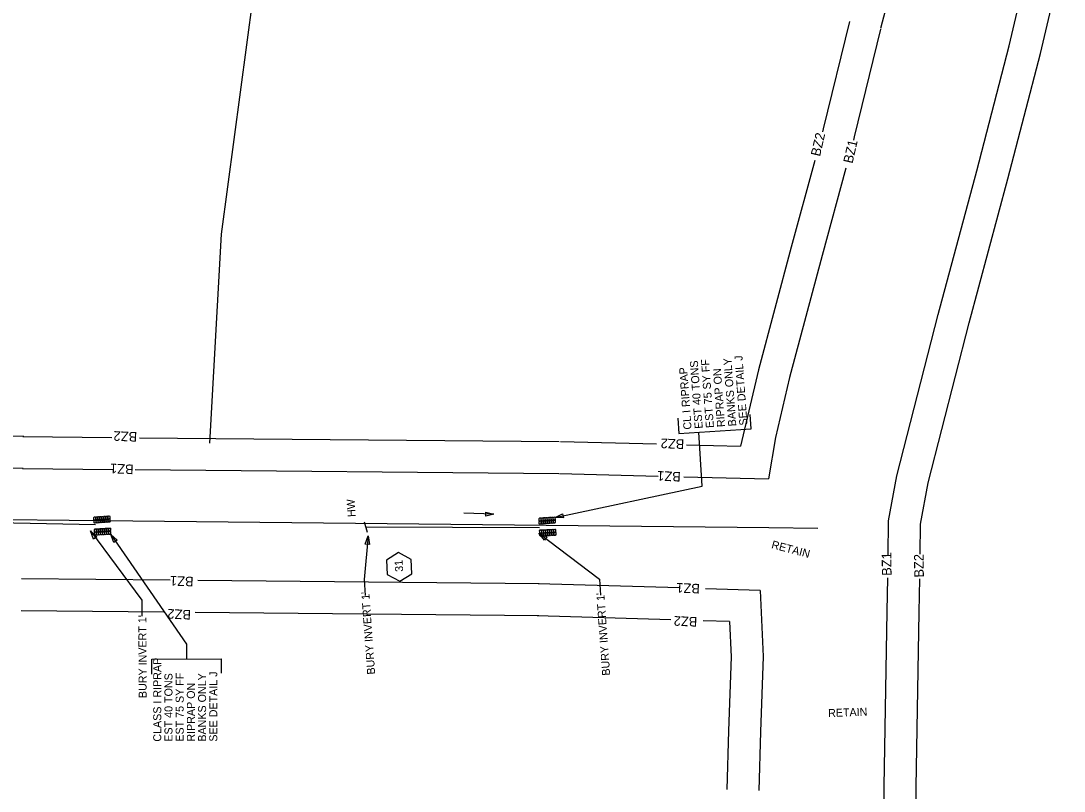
# Model space of a CAD drawing. Extents: x 2384780 to 2405432, y 547869 to 573706.
# Drawn here: x 2395243 to 2395895, y 555848 to 556329 of the extents above; entities that cross this region are included whole.
import ezdxf

# ---------------------------------------------------------------- set-up
doc = ezdxf.new("R2010")
doc.units = 0
for name, color, linetype in [('Old_Level_1', 7, 'Continuous'), ('Old_Level_19', 7, 'Continuous'), ('Old_Level_23', 7, 'Continuous'), ('Old_Level_5', 7, 'Continuous'), ('Old_Level_6', 7, 'Continuous'), ('Prop Buffer Zone 1', 7, 'Continuous'), ('Prop Buffer Zone 2', 7, 'Continuous'), ('Prop Drainage Box Number Symbol CELL', 7, 'Continuous'), ('Prop Drop Inlet Text', 7, 'Continuous')]:
    doc.layers.add(name, color=color, linetype=linetype)

# ---------------------------------------------------------------- blocks, each defined once
blk = doc.blocks.new('AH1')
at = {"layer": 'Old_Level_23'}
blk.add_lwpolyline([(-5.28, 1.32), (0, 0), (-5.28, -1.32)], close=True, dxfattribs=at)
blk = doc.blocks.new('RRA')
at = {"layer": 'Old_Level_1'}
for p, q in [((0, 0.078), (0.2, 0.078)), ((0, 0.04), (0.2, 0.04)), ((0.2, -0.04), (0, -0.04)), ((0.2, -0.078), (0, -0.078))]:
    blk.add_line(p, q, dxfattribs=at)
for points in [[(0.0235, 0.115), (0.025, 0.103), (0.025, 0.0815), (0.01, 0.0745), (0, 0.078), (0.0015, 0.1065), (0.01175, 0.115), (0.0235, 0.115)], [(0.0235, 0.077), (0.025, 0.065), (0.025, 0.0435), (0.01, 0.0365), (0, 0.04), (0.0015, 0.0685), (0.01175, 0.077), (0.0235, 0.077)], [(0.0485, 0.115), (0.05025, 0.103), (0.05025, 0.0815), (0.035, 0.0745), (0.025, 0.078), (0.02675, 0.1065), (0.037, 0.115), (0.0485, 0.115)], [(0.0485, 0.077), (0.05025, 0.065), (0.05025, 0.0435), (0.035, 0.0365), (0.025, 0.04), (0.02675, 0.0685), (0.037, 0.077), (0.0485, 0.077)], [(0.07375, 0.115), (0.0755, 0.103), (0.0755, 0.0815), (0.06025, 0.0745), (0.05025, 0.078), (0.052, 0.1065), (0.062, 0.115), (0.07375, 0.115)], [(0.07375, 0.077), (0.0755, 0.065), (0.0755, 0.0435), (0.06025, 0.0365), (0.05025, 0.04), (0.052, 0.0685), (0.062, 0.077), (0.07375, 0.077)], [(0.099, 0.115), (0.1005, 0.103), (0.1005, 0.0815), (0.0855, 0.0745), (0.0755, 0.078), (0.077, 0.1065), (0.087, 0.115), (0.099, 0.115)], [(0.099, 0.077), (0.1005, 0.065), (0.1005, 0.0435), (0.0855, 0.0365), (0.0755, 0.04), (0.077, 0.0685), (0.087, 0.077), (0.099, 0.077)], [(0.124, 0.115), (0.1255, 0.103), (0.1255, 0.0815), (0.1105, 0.0745), (0.1005, 0.078), (0.102, 0.1065), (0.11225, 0.115), (0.124, 0.115)], [(0.124, 0.077), (0.1255, 0.065), (0.1255, 0.0435), (0.1105, 0.0365), (0.1005, 0.04), (0.102, 0.0685), (0.11225, 0.077), (0.124, 0.077)], [(0.149, 0.115), (0.15075, 0.103), (0.15075, 0.0815), (0.1355, 0.0745), (0.1255, 0.078), (0.12725, 0.1065), (0.1375, 0.115), (0.149, 0.115)], [(0.149, 0.077), (0.15075, 0.065), (0.15075, 0.0435), (0.1355, 0.0365), (0.1255, 0.04), (0.12725, 0.0685), (0.1375, 0.077), (0.149, 0.077)], [(0.17425, 0.115), (0.176, 0.103), (0.176, 0.0815), (0.16075, 0.0745), (0.15075, 0.078), (0.1525, 0.1065), (0.1625, 0.115), (0.17425, 0.115)], [(0.17425, 0.077), (0.176, 0.065), (0.176, 0.0435), (0.16075, 0.0365), (0.15075, 0.04), (0.1525, 0.0685), (0.1625, 0.077), (0.17425, 0.077)], [(0.1995, 0.115), (0.201, 0.103), (0.201, 0.0815), (0.186, 0.0745), (0.176, 0.078), (0.1775, 0.1065), (0.1875, 0.115), (0.1995, 0.115)], [(0.1995, 0.077), (0.201, 0.065), (0.201, 0.0435), (0.186, 0.0365), (0.176, 0.04), (0.1775, 0.0685), (0.1875, 0.077), (0.1995, 0.077)], [(0.0005, -0.077), (-0.001, -0.065), (-0.001, -0.0435), (0.014, -0.0365), (0.024, -0.04), (0.0225, -0.0685), (0.0125, -0.077), (0.0005, -0.077)], [(0.0005, -0.115), (-0.001, -0.103), (-0.001, -0.0815), (0.014, -0.0745), (0.024, -0.078), (0.0225, -0.1065), (0.0125, -0.115), (0.0005, -0.115)], [(0.02575, -0.077), (0.024, -0.065), (0.024, -0.0435), (0.03925, -0.0365), (0.04925, -0.04), (0.0475, -0.0685), (0.0375, -0.077), (0.02575, -0.077)], [(0.02575, -0.115), (0.024, -0.103), (0.024, -0.0815), (0.03925, -0.0745), (0.04925, -0.078), (0.0475, -0.1065), (0.0375, -0.115), (0.02575, -0.115)], [(0.051, -0.077), (0.04925, -0.065), (0.04925, -0.0435), (0.0645, -0.0365), (0.0745, -0.04), (0.07275, -0.0685), (0.0625, -0.077), (0.051, -0.077)], [(0.051, -0.115), (0.04925, -0.103), (0.04925, -0.0815), (0.0645, -0.0745), (0.0745, -0.078), (0.07275, -0.1065), (0.0625, -0.115), (0.051, -0.115)], [(0.076, -0.077), (0.0745, -0.065), (0.0745, -0.0435), (0.0895, -0.0365), (0.0995, -0.04), (0.098, -0.0685), (0.08775, -0.077), (0.076, -0.077)], [(0.076, -0.115), (0.0745, -0.103), (0.0745, -0.0815), (0.0895, -0.0745), (0.0995, -0.078), (0.098, -0.1065), (0.08775, -0.115), (0.076, -0.115)], [(0.101, -0.077), (0.0995, -0.065), (0.0995, -0.0435), (0.1145, -0.0365), (0.1245, -0.04), (0.123, -0.0685), (0.113, -0.077), (0.101, -0.077)], [(0.101, -0.115), (0.0995, -0.103), (0.0995, -0.0815), (0.1145, -0.0745), (0.1245, -0.078), (0.123, -0.1065), (0.113, -0.115), (0.101, -0.115)], [(0.12625, -0.077), (0.1245, -0.065), (0.1245, -0.0435), (0.13975, -0.0365), (0.14975, -0.04), (0.148, -0.0685), (0.138, -0.077), (0.12625, -0.077)], [(0.12625, -0.115), (0.1245, -0.103), (0.1245, -0.0815), (0.13975, -0.0745), (0.14975, -0.078), (0.148, -0.1065), (0.138, -0.115), (0.12625, -0.115)], [(0.1515, -0.077), (0.14975, -0.065), (0.14975, -0.0435), (0.165, -0.0365), (0.175, -0.04), (0.17325, -0.0685), (0.163, -0.077), (0.1515, -0.077)], [(0.1515, -0.115), (0.14975, -0.103), (0.14975, -0.0815), (0.165, -0.0745), (0.175, -0.078), (0.17325, -0.1065), (0.163, -0.115), (0.1515, -0.115)], [(0.1765, -0.077), (0.175, -0.065), (0.175, -0.0435), (0.19, -0.0365), (0.2, -0.04), (0.1985, -0.0685), (0.18825, -0.077), (0.1765, -0.077)], [(0.1765, -0.115), (0.175, -0.103), (0.175, -0.0815), (0.19, -0.0745), (0.2, -0.078), (0.1985, -0.1065), (0.18825, -0.115), (0.1765, -0.115)]]:
    blk.add_lwpolyline(points, dxfattribs=at)

msp = doc.modelspace()

# ---------------------------------------------------------------- linework, layer by layer
at = {"layer": 'Old_Level_1'}
for p, q in [((2395668.94, 556038.78), (2395666.85, 556072.54)), ((2395290.01, 556014.67), (2395141.67, 556017.68)), ((2395567.4, 556012.8), (2395458.75, 556013.24)), ((2395346.77, 555940.04), (2395346.81, 555930.81))]:
    msp.add_line(p, q, dxfattribs=at)
for points in [[(2395653.73, 556081.15), (2395654.34, 556071.73), (2395699.66, 556074.63), (2395699.09, 556083.46)], [(2395286.91, 556010.88), (2395318.94, 555967.55), (2395318.98, 555957.55)], [(2395567.05, 556009.32), (2395604.93, 555980.61), (2395605.55, 555970.63)], [(2395460.33, 556007.74), (2395457.88, 555980.38), (2395458.5, 555970.4)], [(2395325.12, 555921.37), (2395325.12, 555930.8), (2395368.5, 555930.82), (2395368.51, 555921.98)]]:
    msp.add_lwpolyline(points, dxfattribs=at)
at = {"layer": 'Old_Level_19'}
for p, q in [((2395401.03, 556438.8), (2395368.55, 556196.08)), ((2395368.55, 556196.08), (2395361.32, 556065.62))]:
    msp.add_line(p, q, dxfattribs=at)
at = {"layer": 'Old_Level_5'}
for p, q in [((2395577.2, 556019.2), (2395668.94, 556038.78)), ((2395457.86, 556016.4), (2395459.64, 556009.94)), ((2395538.91, 556021.18), (2395520.13, 556021.83)), ((2395299.65, 556008.48), (2395346.77, 555940.04))]:
    msp.add_line(p, q, dxfattribs=at)
for points in [[(2395533.95, 556022.6), (2395538.91, 556021.18), (2395533.87, 556020.1)], [(2395582.36, 556019.02), (2395577.2, 556019.2), (2395581.83, 556021.46)], [(2395301.42, 556003.64), (2395299.65, 556008.48), (2395303.49, 556005.04)]]:
    msp.add_lwpolyline(points, close=True, dxfattribs=at)
at = {"layer": 'Old_Level_6'}
msp.add_lwpolyline([(2394796.41, 556022.42), (2395710.73, 556012.84), (2395741.36, 556012.58)], dxfattribs=at)
at = {"layer": 'Prop Buffer Zone 1'}
for points in [[(2395780.55, 556324.67), (2395841.99, 556557.11)], [(2395785.1, 555995.55), (2395785.39, 556017.1), (2395790.69, 556045.15), (2395816.45, 556145.92), (2395840.54, 556235.73), (2395860.89, 556313.74), (2395870.85, 556356.35), (2395875.74, 556375.04)], [(2395780.41, 556324.12), (2395764.02, 556256.93), (2395763.45, 556254.81)], [(2395758.69, 556237.25), (2395743.95, 556182.82), (2395723.55, 556106.57), (2395714.76, 556069.06), (2395710.48, 556043.32)], [(2395244.75, 556049.69), (2394918.67, 556057.18)], [(2395244.33, 556049.69), (2395301.08, 556049.18)], [(2395314.75, 556049.06), (2395579.42, 556046.66)], [(2395579.91, 556046.65), (2395641.46, 556045.08)], [(2395657.53, 556044.67), (2395710.48, 556043.32)], [(2395336.62, 555980.02), (2395243.75, 555980.9)], [(2395567.22, 555977.83), (2395353.92, 555979.85)], [(2395654.81, 555975.17), (2395566.6, 555977.84)], [(2395782.67, 555851.11), (2395784.63, 555960.44), (2395784.91, 555981.4)], [(2395705.27, 555973.65), (2395671.04, 555974.68)], [(2395705.27, 555973.65), (2395707.03, 555932.35), (2395705.46, 555885.26), (2395704.5, 555848.71)], [(2395782.7, 555730.8), (2395782.68, 555851.65)]]:
    msp.add_lwpolyline(points, dxfattribs=at)
at = {"layer": 'Prop Buffer Zone 2'}
for points in [[(2395805.11, 555996.18), (2395805.36, 556015.1), (2395810.22, 556040.81), (2395835.79, 556140.85), (2395859.88, 556230.62), (2395880.31, 556308.94), (2395890.27, 556351.54), (2395895.13, 556370.15)], [(2395760.98, 556328.86), (2395744.65, 556261.92), (2395744.12, 556259.95)], [(2395739.29, 556242.12), (2395724.64, 556188.02), (2395704.15, 556111.44), (2395692.97, 556063.77)], [(2395245.21, 556069.68), (2394921.22, 556077.12)], [(2395244.51, 556069.69), (2395300.2, 556069.19)], [(2395317.43, 556069.03), (2395579.6, 556066.66)], [(2395580.42, 556066.65), (2395640.47, 556065.11)], [(2395659.13, 556064.64), (2395692.97, 556063.77)], [(2395802.67, 555850.75), (2395804.62, 555960.12), (2395804.9, 555980.89)], [(2395332.62, 555960.06), (2395243.56, 555960.9)], [(2395567.03, 555957.83), (2395352.23, 555959.87)], [(2395649.49, 555955.33), (2395565.99, 555957.85)], [(2395686.08, 555954.22), (2395669.56, 555954.72)], [(2395686.08, 555954.22), (2395687.02, 555932.25), (2395685.47, 555885.85), (2395684.51, 555849.24)], [(2395802.7, 555730.8), (2395802.68, 555851.65)]]:
    msp.add_lwpolyline(points, dxfattribs=at)
at = {"layer": 'Prop Drainage Box Number Symbol CELL'}
msp.add_lwpolyline([(2395480.06, 555979.33), (2395487.64, 555984.1), (2395487.29, 555993.05), (2395479.38, 555997.22), (2395471.8, 555992.45), (2395472.15, 555983.51)], close=True, dxfattribs=at)

# ---------------------------------------------------------------- block references
at = {"layer": 'Old_Level_23', "xscale": 0.9999976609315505, "yscale": 0.9999976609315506, "rotation": 142.84291188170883}
msp.add_blockref('AH1', (2395567.05, 556009.32), dxfattribs=at)
at = {"layer": 'Old_Level_5'}
for name, p, xscale, yscale, rotation in [('RRA', (2395299.2, 556014.42), 50.00000000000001, 49.99999999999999, -176.45568333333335), ('RRA', (2395577.33, 556013.78), 50.00000000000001, 49.99999999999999, -176.45568333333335), ('AH1', (2395286.91, 556010.88), 0.9999983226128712, 0.9999983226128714, 123.4658574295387), ('AH1', (2395460.33, 556007.74), 0.9999975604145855, 0.9999975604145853, 84.88709567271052)]:
    msp.add_blockref(name, p, dxfattribs=dict(at, xscale=xscale, yscale=yscale, rotation=rotation))

# ---------------------------------------------------------------- texts
at = {"layer": 'Old_Level_1'}
for s, rotation, p in [('SEE DETAIL J', 94.17154, (2395697.32, 556076.8)), ('EST 40 TONS ', 94.17154, (2395669.39, 556074.77)), ('EST 75 SY FF', 94.17154, (2395676.37, 556075.27)), ('BANKS ONLY', 94.17154, (2395690.34, 556076.29)), ('CL I RIPRAP', 94.17154, (2395662.41, 556074.26)), ('RIPRAP ON', 94.17154, (2395683.35, 556075.78)), ('RETAIN', 345.23587, (2395711.92, 556000.09)), ("BURY INVERT 1'", 94.17154, (2395464.76, 555921.29)), ("BURY INVERT 1'", 94.17154, (2395611.57, 555920.62)), ("BURY INVERT 1'", 90.23015, (2395321.98, 555906.4)), ('RETAIN', 2.25349, (2395747.78, 555894.51))]:
    msp.add_text(s, height=5, rotation=rotation, dxfattribs=at).set_placement(p)
at = {"layer": 'Old_Level_5'}
for s, rotation, p in [('HW', 93.59359, (2395452.5, 556019.65)), ('CLASS I RIPRAP', 90, (2395331.09, 555879.19)), ('EST 40 TONS', 90, (2395338.09, 555879.19)), ('EST 75 SY FF', 90, (2395345.09, 555879.19)), ('BANKS ONLY', 90, (2395359.09, 555879.19)), ('SEE DETAIL J', 90, (2395366.09, 555879.19)), ('RIPRAP ON', 90, (2395352.09, 555879.19))]:
    msp.add_text(s, height=5, rotation=rotation, dxfattribs=at).set_placement(p)
at = {"layer": 'Prop Buffer Zone 1'}
for rotation, p in [(77.03589, (2395762.91, 556239.93)), (177.37747, (2395313.95, 556052.18)), (177.37747, (2395655.75, 556047.56)), (90.8948, (2395787.34, 555982.81)), (177.37747, (2395351.39, 555982.06)), (177.37747, (2395667.69, 555977.66))]:
    msp.add_text('BZ1', height=6, rotation=rotation, dxfattribs=at).set_placement(p)
at = {"layer": 'Prop Buffer Zone 2'}
for rotation, p in [(77.03589, (2395742.61, 556244.33)), (177.37747, (2395316.13, 556072.47)), (177.37747, (2395657.92, 556067.86)), (90.8948, (2395807.53, 555981.73)), (177.37747, (2395349.77, 555961.38)), (177.37747, (2395666.07, 555956.98))]:
    msp.add_text('BZ2', height=6, rotation=rotation, dxfattribs=at).set_placement(p)
at = {"layer": 'Prop Drop Inlet Text'}
msp.add_text('31', height=5, rotation=93.59359, dxfattribs=at).set_placement((2395482.25, 555985.42))

doc.saveas('drawing.dxf')
